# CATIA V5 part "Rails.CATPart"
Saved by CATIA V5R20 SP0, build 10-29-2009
Part number: 2
Bounding box of the stored display mesh (mm): x -20 to 20, y -20 to 20, z 0 to 600
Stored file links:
  C:\Users\halimelbaba\Documents\cmv\projet\Rails.CATPart
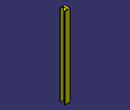
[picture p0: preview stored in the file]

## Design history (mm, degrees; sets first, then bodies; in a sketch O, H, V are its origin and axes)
Body1 (main body)
  Sketch1 on xy-plane, origin (0, 0, 0), H (1, 0, 0), V (0, 1, 0)
    line L1 (-20, 20) -> (20, 20)
    line L2 (20, 20) -> (20, -20)
    line L3 (20, -20) -> (-20, -20)
    line L4 (-20, -20) -> (-20, 20)
    distance L1 L3 = 40
    distance L2 L4 = 40
    horizontal: L1 H, L3 H
    vertical: L2 V, L4 V
    symmetry: L3 L1 H, L2 L4 V
  Pad1: profile Sketch1, direction (0, 0, 1), length 600
  Plane1: type Offset, RefPlane end face of Pad1, Offset 0, reversed
  Sketch2 on Plane1, origin (0, 0, 600), H (1, 0, 0), V (0, -1, 0)
    line L1 (20, 16) -> (-5, 16)
    line L2 (-5, 16) -> (-5, -16)
    line L3 (-5, -16) -> (20, -16)
    line L4 (20, -16) -> (20, 16)
    reference projected line E1 (20, 17.5) -> (20, -17.5) from edge [start face of Pad1 | face of Pad1 from Sketch1.L2]
    reference projected line E2 (20, -20) -> (-20, -20) from edge [start face of Pad1 | face of Pad1 from Sketch1.L1]
    reference projected line E3 (-20, -20) -> (-20, 20) from edge [start face of Pad1 | face of Pad1 from Sketch1.L4]
    distance L3 E2 = 4
    distance L2 E3 = 15
    horizontal: L1 H, L3 H
    vertical: L2 V, L4 V
    symmetry: L3 L1 H
    coincidence: L4 E1
  Pocket1: profile Sketch2, direction (0, 0, -1), up to start face of Pad1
